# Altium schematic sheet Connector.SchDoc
size A3; Organization: ORGANIZATION; Address1: ADDRESS 1; Address2: ADDRESS 2; Address3: ADDRESS 3; Address4: ADDRESS 4; Revision: -; SheetNumber: 1; SheetTotal: 4; ENG_APP_DATE: --/--/--; DSN_APP_DATE: --/--/--; CHK_APP_DATE: --/--/--
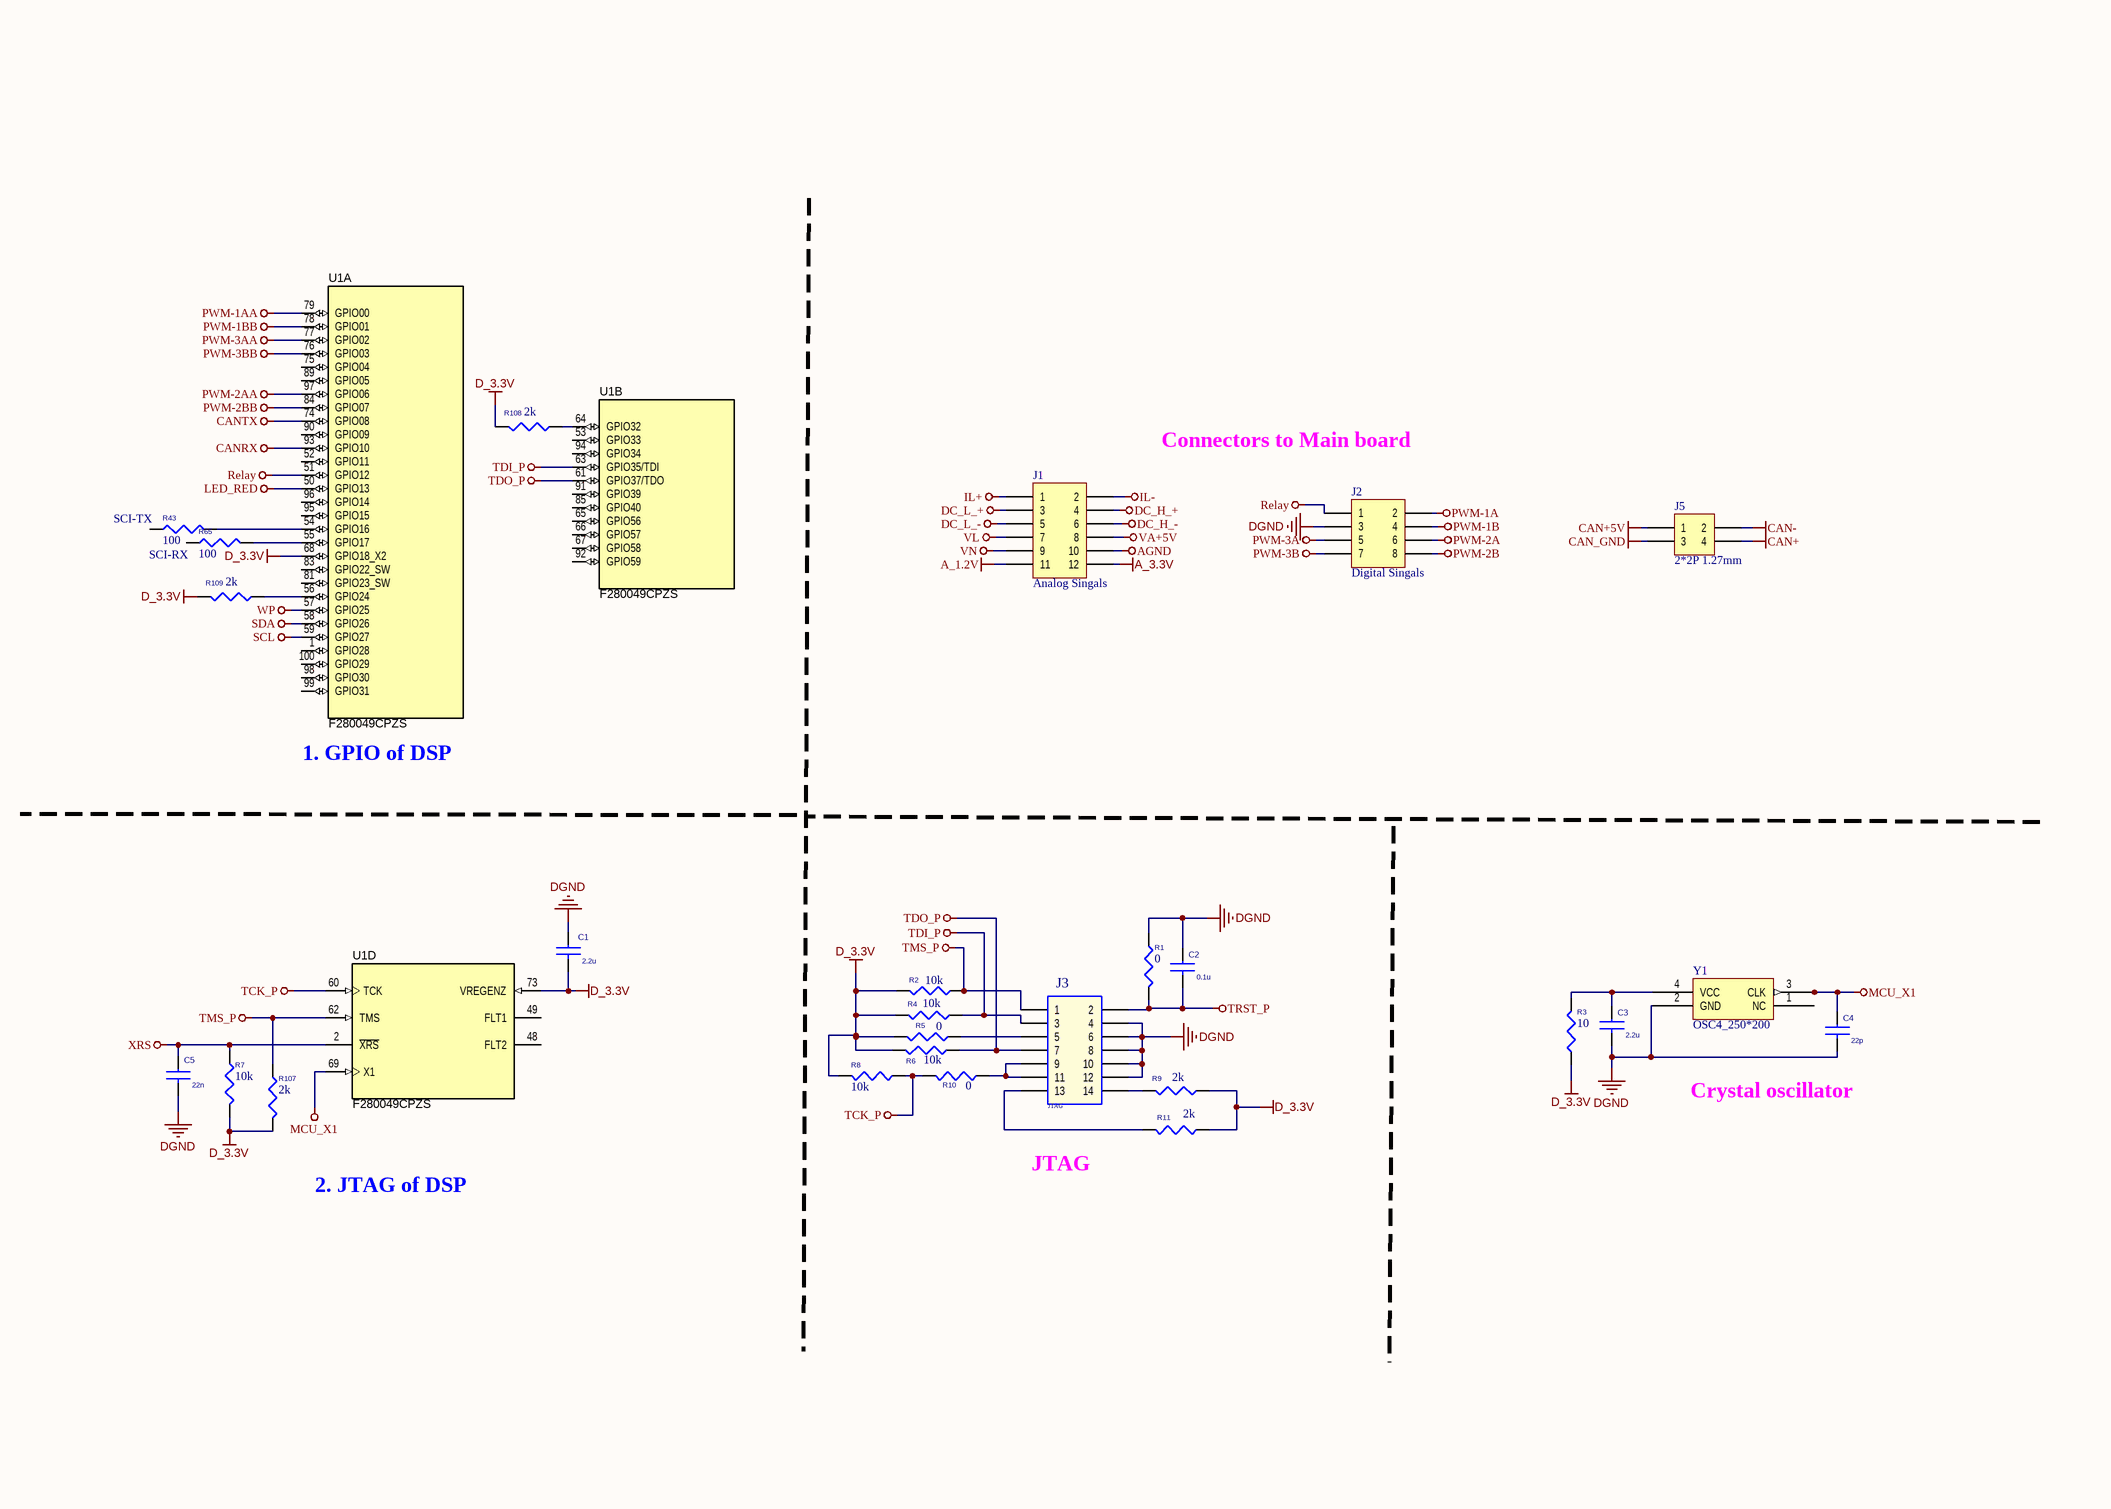
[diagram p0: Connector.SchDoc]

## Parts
C1  2.2u  [C0402]
C2  0.1u  [C0402]
C3  2.2u  [C0402]
C4  22p  [C0402]
C5  22n  [C0402]
J1  Analog Singals  [HDR2X6H-254MM-90]
J2  Digital Singals  [HDR2X4H-254MM-90]
J3  JTAG  [HDR2X7H-254MM]
J5  2*2P 1.27mm  [HDR2X2H-254MM-90]
R1  0  [R0402]
R2  10k  [R0402]
R3  10  [R0402]
R4  10k  [R0402]
R5  0  [R0402]
R6  10k  [R0402]
R7  10k  [R0402]
R8  10k  [R0402]
R9  2k  [R0402]
R10  0  [R0402]
R11  2k  [R0402]
R43  100  [R0402]
R65  100  [R0402]
R107  2k  [R0402]
R108  2k  [R0402]
R109  2k  [R0402]
U1  F280049CPZS  [PZ0100A_N]  (parts A,B,D of 5)
Y1  OSC4_250*200  [TBD-Footprint-1]

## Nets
A_1.2V: J1.11
A_3.3V: J1.12
AGND: J1.10
CAN+: J5.4
CAN+5V: J5.1
CAN-: J5.2
CAN_GND: J5.3
CANRX: U1.93(GPIO10)
CANTX: U1.74(GPIO08)
D_3.3V: C1.2 R2.2 R3.1 R4.2 R5.2 R6.2 R7.2 R8.2 R9.1 R11.1 R107.2 R108.2 R109.2 U1.68(GPIO18_X2) U1.73(VREGENZ)
DC_H_+: J1.4
DC_H_-: J1.6
DC_L_+: J1.3
DC_L_-: J1.5
DGND: C1.1 C2.1 C3.2 C4.2 C5.2 J2.3 J3.4 J3.6 J3.8 J3.10 J3.12 R1.1 Y1.2(GND)
IL+: J1.1
IL-: J1.2
LED_RED: U1.50(GPIO13)
MCU_X1: C4.1 U1.69(X1) Y1.3(CLK)
PWM-1A: J2.2
PWM-1AA: U1.79(GPIO00)
PWM-1B: J2.4
PWM-1BB: U1.78(GPIO01)
PWM-2A: J2.6
PWM-2AA: U1.97(GPIO06)
PWM-2B: J2.8
PWM-2BB: U1.84(GPIO07)
PWM-3A: J2.5
PWM-3AA: U1.77(GPIO02)
PWM-3B: J2.7
PWM-3BB: U1.76(GPIO03)
Relay: J2.1 U1.51(GPIO12)
SCL: U1.59(GPIO27)
SDA: U1.58(GPIO26)
TCK_P: R8.1 R10.2 U1.60(TCK)
TDI_P: J3.3 R4.1 U1.63(GPIO35/TDI)
TDO_P: J3.7 R6.1 U1.61(GPIO37/TDO)
TMS_P: J3.1 R2.1 R107.1 U1.62(TMS)
TRST_P: C2.2 J3.2 R1.2
VA+5V: J1.8
VL: J1.7
VN: J1.9
WP: U1.57(GPIO25)
XRS: C5.1 R7.1 U1.2(~{XRS})
NetC3_1: C3.1 R3.2 Y1.4(VCC)
NetJ3_5: J3.5 R5.1
NetJ3_9: J3.9 J3.11 R10.1
NetJ3_13: J3.13 R11.2
NetJ3_14: J3.14 R9.2
NetR43_2: R43.2 U1.54(GPIO16)
NetR65_2: R65.2 U1.55(GPIO17)
NetR108_1: R108.1 U1.64(GPIO32)
NetR109_1: R109.1 U1.56(GPIO24)

Not connected (* = marked no-connect by the designer): R43 1; R65 1; U1 1(GPIO28) 48(FLT2) 49(FLT1) 52(GPIO11) 53(GPIO33) 65(GPIO56) 66(GPIO57) 67(GPIO58) 75(GPIO04) 81(GPIO23_SW) 83(GPIO22_SW) 85(GPIO40) 89(GPIO05) 90(GPIO09) 91(GPIO39) 92(GPIO59) 94(GPIO34) 95(GPIO15) 96(GPIO14) 98(GPIO30) 99(GPIO31) 100(GPIO29); Y1 1(NC)

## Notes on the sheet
- Connectors to Main board
- (near R43) SCI-TX
- SCI-RX
- (near U1) 1. GPIO of DSP
- (near C4) Crystal oscillator
- 2. JTAG of DSP
- JTAG

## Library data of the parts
C1 C3 = CAP NP_Dup1: CAP CER 2.2UF 25V JB 0402; PCB Footprint: C1206
C2 = CAP NP_Dup1: CAP CER 0.1UF 25V X7R 0402; PCB Footprint: C1206
C4 = CAP NP_Dup1: CAP CER 22PF 25V C0G/NP0 0402; PCB Footprint: C1206
C5 = CAP NP_Dup1: CAP CER 0.022UF 25V X7R 0402; PCB Footprint: C1206
J1 = J12: 2*6P 1.27mm
J2 = J8_8P: 2*4P 1.27mm
J3 = 2*7P: 2*7P 1.27mm; Part number: 621000812; Part_Name: Á¬½ÓÆ÷; Part Label: 2*7P 2.54 Ö±Õë; PCB Footprint: con_2mm54_7x2; Unit: PCS
J5 = CAN
R1 R5 R10 = RESISTOR_Dup1: PCB Footprint: R0603
R2 R4 R6-R8 = RESISTOR_Dup1: RES 10K OHM 1% 1/8W 0402; PCB Footprint: R0603
R3 = RESISTOR_Dup1: RES 10 OHM 1% 1/8W 0402; PCB Footprint: R0603
R9 R11 R107-R109 = RESISTOR_Dup1: RCC0402 100 2K0 1% ET7 E3; PCB Footprint: R0603
R43 R65 = RESISTOR_Dup1: RES 0.1 OHM 5% 1/8W 0402; PCB Footprint: R0603
U1 = CMP-0078352-1: Piccolo Microcontroller, PZ0100A (LQFP-100); Manufacturer: Texas Instruments; SizeArea_mm2: 256; SizeAreaWB_mm2: 324; SizeX_mm: 16; SizeZ_mm: 1.6; CompType: IC; AEC Category: Q200; AEC Qualified: N
Y1 = CMP-003-00030-2: HCMOS Output Clock Oscillator, 10MHz Nom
